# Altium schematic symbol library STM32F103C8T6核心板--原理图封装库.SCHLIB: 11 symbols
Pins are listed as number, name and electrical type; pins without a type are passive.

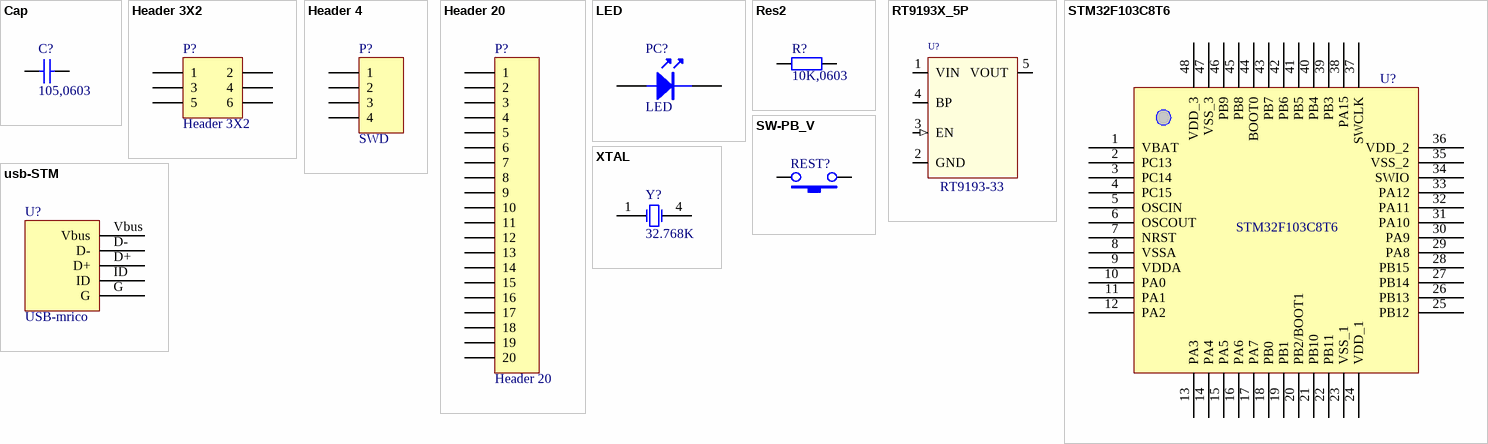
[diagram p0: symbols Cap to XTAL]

## Cap
designator C?, comment 105,0603
Capacitor; Value: 104
footprint CC2012-0805 (Chip Capacitor; Body 2.0 x 1.2 mm (LxW typ))
footprint CAPR2.54-5.1x3.2 (Capacitor, Ceramic, Thru-Hole, Dipped Radial; Body 5.1 x 3.2 mm (WxT) Pin Spacing 2.54 mm (typ))
footprint CAPR5.08-7.8x3.2 (Capacitor, Ceramic, Thru-Hole, Dipped Radial; Body 7.8 x 3.2 mm (WxT) Pin Spacing 5.08 mm (typ))
simulation model CAP (Capacitor)
signal-integrity model Cap
footprint C0603
pins: 1, 2

## Header 3X2
designator P?
Header, 3-Pin, Dual row
footprint HDR2X3 (Connector; Header; 3x2 Position)
signal-integrity model Connector
pins: 1, 2, 3, 4, 5, 6

## Header 4
designator P?, comment SWD
Header, 4-Pin
footprint HDR1X4 (Connector; Header; 4 Position)
signal-integrity model Connector
pins: 1, 2, 3, 4

## Header 20
designator P?
Header, 20-Pin
footprint HDR1X20 (Connector; Header; 20 Position)
signal-integrity model Connector
pins: 1, 2, 3, 4, 5, 6, 7, 8, 9, 10, 11, 12, 13, 14, 15, 16, 17, 18, 19, 20

## LED
designator PC?
footprint LED; pin to pad A>1 K>2
pins: A 1, K 2

## Res2
designator R?, comment 10K,0603
Resistor
footprint CR2012-0805 (Chip Resistor; Body 2.0 x 1.3 mm (LxW typ))
simulation model RESISTOR (Resistor)
signal-integrity model Res
footprint R0603
pins: 1, 2

## RT9193X_5P
designator U?, comment RT9193-33
ICA_MFR_NAME: RICHTEK; ICA_PARTNUM: $$2191094$$RT9193-15CU5; Part Number: TMP-13
footprint SOT-23-5
pins: 1 VIN (power), 2 GND (power), 3 EN (in), 4 BP, 5 VOUT (power)

## STM32F103C8T6
designator U?
footprint 48P
pins: 1 VBAT, 2 PC13, 3 PC14, 4 PC15, 5 OSCIN, 6 OSCOUT, 7 NRST, 8 VSSA, 9 VDDA, 10 PA0, 11 PA1, 12 PA2, 13 PA3, 14 PA4, 15 PA5, 16 PA6, 17 PA7, 18 PB0, 19 PB1, 20 PB2/BOOT1, 21 PB10, 22 PB11, 23 VSS_1, 24 VDD_1, 25 PB12, 26 PB13, 27 PB14, 28 PB15, 29 PA8, 30 PA9, 31 PA10, 32 PA11, 33 PA12, 34 SWIO, 35 VSS_2, 36 VDD_2, 37 SWCLK, 38 PA15, 39 PB3, 40 PB4, 41 PB5, 42 PB6, 43 PB7, 44 BOOT0, 45 PB8, 46 PB9, 47 VSS_3, 48 VDD_3

## SW-PB_V
designator REST?
SWITCH
footprint KEY-SMT
footprint SW/4/SMT
footprint SW/2/R1
footprint KEY/01
pins: 1, 2

## usb-STM
designator U?, comment USB-mrico
footprint Micro_USB
pins: D+, D-, G, ID, Vbus

## XTAL
designator Y?, comment 32.768K
Crystal Oscillator
footprint X/2.5/2/6/2.5
simulation model XTAL (Spice Subcircuit)
pins: 1 OSC1, 4 OSC2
